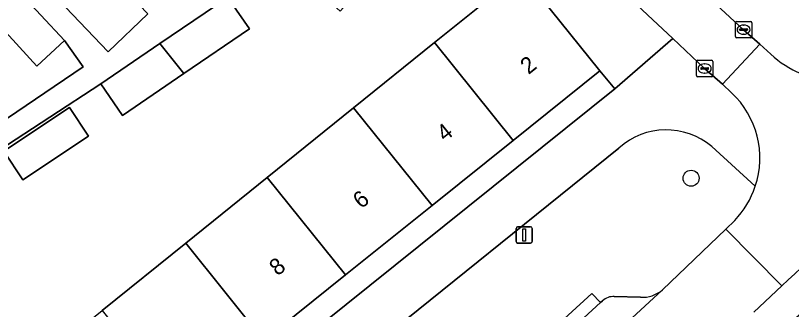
# Model space of a CAD drawing. Extents: x 162344 to 162869, y 381217 to 381818.
# Drawn here: x 162593.1 to 162640.44, y 381609.01 to 381626.94 of the extents above; entities that cross this region are included whole.
import ezdxf

# ---------------------------------------------------------------- set-up
doc = ezdxf.new("R2010")
doc.units = 0
for name, color, linetype in [('IMGEO_Boom', 7, 'Continuous'), ('IMGEO_Erf', 7, 'Continuous'), ('IMGEO_Groenvoorziening', 7, 'Continuous'), ('IMGEO_Kolk', 7, 'Continuous'), ('IMGEO_Lichtmast', 7, 'Continuous'), ('IMGEO_Pand', 7, 'Continuous'), ('IMGEO_Pand_nummerreeks', 7, 'Continuous'), ('IMGEO_Parkeervlak_open', 7, 'Continuous'), ('IMGEO_Rijbaan_lokaal_open', 7, 'Continuous'), ('IMGEO_Voetpad_open', 7, 'Continuous')]:
    doc.layers.add(name, color=color, linetype=linetype)

msp = doc.modelspace()

# ---------------------------------------------------------------- linework, layer by layer
at = {"layer": 'IMGEO_Boom'}
msp.add_circle((162634.319, 381617.015), 0.489, dxfattribs=at)
at = {"layer": 'IMGEO_Erf'}
for points in [[(162624.28, 381630.339), (162618.835, 381635.59), (162615.058, 381631.44), (162615.96, 381630.598), (162612.904, 381627.212), (162609.777, 381630.035), (162606.262, 381627.745), (162607.37, 381626.124), (162603.382, 381623.399), (162599.633, 381620.838), (162598.316, 381622.766), (162588.949, 381616.664), (162591.647, 381613.341), (162588.696, 381610.944), (162585.998, 381614.267), (162585.08, 381613.516), (162586.977, 381611.168), (162582.48, 381607.587), (162588.265, 381600.781), (162593.384, 381604.909), (162598.393, 381608.947), (162603.495, 381613.061), (162608.464, 381617.068), (162613.728, 381621.312)], [(162573.509, 381631.921), (162578.281, 381626.025), (162582.965, 381620.237), (162586.145, 381616.308), (162597.224, 381623.819), (162596.092, 381625.415), (162594.412, 381623.857), (162591.426, 381627.075)], [(162613.728, 381621.312), (162618.667, 381625.295), (162623.946, 381629.551), (162624.231, 381629.81)]]:
    msp.add_lwpolyline(points, dxfattribs=at)
for points in [[(162629.662, 381622.463), (162628.75, 381623.566), (162623.462, 381619.322), (162618.513, 381615.351), (162613.24, 381611.118), (162608.261, 381607.123), (162603.15, 381603.02), (162598.133, 381598.994), (162593.003, 381594.877), (162593.892, 381593.755)], [(162597.561, 381619.576), (162596.851, 381619.103), (162596.529, 381618.889), (162593.556, 381616.907), (162592.387, 381618.661), (162596.391, 381621.33)]]:
    msp.add_lwpolyline(points, close=True, dxfattribs=at)
at = {"layer": 'IMGEO_Groenvoorziening'}
for points in [[(162632.252, 381630.976), (162637.522, 381626.077), (162638.503, 381625.198), (162639.185, 381624.588)], [(162629.916, 381618.858), (162614.116, 381606.124), (162618.384, 381600.939), (162628.272, 381609.975), (162628.789, 381609.425), (162628.918, 381609.544)], [(162638.236, 381616.522), (162635.574, 381618.945)], [(162636.433, 381613.917), (162636.982, 381614.446)], [(162632.571, 381610.208), (162636.433, 381613.917)], [(162629.635, 381609.796), (162631.231, 381609.754)]]:
    msp.add_lwpolyline(points, dxfattribs=at)
for centre, radius, start, end in [((162643.143, 381628.73), 5.729, 226.3053, 248.3061), ((162632.795, 381615.668), 4.297, 49.6956, 132.0663), ((162633.069, 381618.226), 5.441, 315.9882, 341.7439), ((162631.345, 381611.623), 1.873, 266.5245, 310.9088), ((162629.57, 381608.834), 0.964, 86.1469, 132.5826)]:
    msp.add_arc(centre, radius, start, end, dxfattribs=at)
at = {"layer": 'IMGEO_Kolk'}
for p, q in [((162637.021, 381625.651), (162637.021, 381626.503)), ((162637.096, 381626.577), (162637.948, 381626.577)), ((162637.509, 381626.357), (162637.534, 381626.357)), ((162638.022, 381626.503), (162638.022, 381625.651)), ((162637.28, 381626.071), (162637.28, 381626.083)), ((162637.718, 381626.034), (162637.32, 381626.034)), ((162637.323, 381626.12), (162637.721, 381626.12)), ((162637.532, 381625.797), (162637.507, 381625.797)), ((162637.764, 381626.083), (162637.764, 381626.071)), ((162637.948, 381625.577), (162637.096, 381625.577)), ((162634.644, 381623.282), (162634.644, 381624.134)), ((162634.719, 381624.208), (162635.571, 381624.208)), ((162635.132, 381623.988), (162635.157, 381623.988)), ((162635.645, 381624.134), (162635.645, 381623.282)), ((162634.903, 381623.702), (162634.903, 381623.714)), ((162635.341, 381623.665), (162634.943, 381623.665)), ((162634.946, 381623.751), (162635.344, 381623.751)), ((162635.155, 381623.428), (162635.13, 381623.428)), ((162635.387, 381623.714), (162635.387, 381623.702)), ((162635.571, 381623.208), (162634.719, 381623.208))]:
    msp.add_line(p, q, dxfattribs=at)
for points in [[(162637.021, 381625.651), (162637.021, 381626.503)], [(162637.096, 381626.577), (162637.948, 381626.577)], [(162638.022, 381626.503), (162638.022, 381625.651)], [(162637.948, 381625.577), (162637.096, 381625.577)], [(162634.644, 381623.282), (162634.644, 381624.134)], [(162634.719, 381624.208), (162635.571, 381624.208)], [(162635.645, 381624.134), (162635.645, 381623.282)], [(162635.571, 381623.208), (162634.719, 381623.208)]]:
    msp.add_lwpolyline(points, dxfattribs=at)
for centre, radius, start, end in [((162637.098, 381626.501), 0.0765, 91.552, 178.448), ((162637.098, 381626.501), 0.0765, 91.552, 178.448), ((162637.946, 381626.501), 0.0765, 1.552, 88.448), ((162637.946, 381626.501), 0.0765, 1.552, 88.448), ((162637.32, 381626.08), 0.0403, 85.8775, 175.7526), ((162637.317, 381626.07), 0.0366, 178.938, 274.7102), ((162637.721, 381626.077), 0.043, 264.8664, 352.4533), ((162637.725, 381626.082), 0.0386, 1.7309, 96.639), ((162637.098, 381625.653), 0.0765, 181.552, 268.448), ((162637.098, 381625.653), 0.0765, 181.552, 268.448), ((162637.946, 381625.653), 0.0765, 271.552, 358.448), ((162637.946, 381625.653), 0.0765, 271.552, 358.448), ((162634.721, 381624.132), 0.0765, 91.552, 178.448), ((162634.721, 381624.132), 0.0765, 91.552, 178.448), ((162635.569, 381624.132), 0.0765, 1.552, 88.448), ((162635.569, 381624.132), 0.0765, 1.552, 88.448), ((162634.943, 381623.711), 0.0403, 85.8775, 175.7526), ((162634.94, 381623.701), 0.0366, 178.938, 274.7102), ((162635.344, 381623.708), 0.043, 264.8664, 352.4533), ((162635.348, 381623.713), 0.0386, 1.7309, 96.639), ((162634.721, 381623.284), 0.0765, 181.552, 268.448), ((162634.721, 381623.284), 0.0765, 181.552, 268.448), ((162635.569, 381623.284), 0.0765, 271.552, 358.448), ((162635.569, 381623.284), 0.0765, 271.552, 358.448)]:
    msp.add_arc(centre, radius, start, end, dxfattribs=at)
for centre, major_axis, ratio, start_param, end_param in [((162637.508, 381626.077), (-0.387, 0.002), 0.722429, 4.712389, 7.853982), ((162637.533, 381626.077), (-0.39, 0.002), 0.717154, 1.570796, 4.712389), ((162635.131, 381623.708), (-0.387, 0.002), 0.722429, 4.712389, 7.853982), ((162635.156, 381623.708), (-0.39, 0.002), 0.717154, 1.570796, 4.712389)]:
    msp.add_ellipse(centre, major_axis=major_axis, ratio=ratio, start_param=start_param, end_param=end_param, dxfattribs=at)
at = {"layer": 'IMGEO_Lichtmast'}
for p, q in [((162623.637, 381613.157), (162623.637, 381613.957)), ((162623.637, 381613.957), (162623.637, 381613.157)), ((162623.737, 381614.057), (162624.527, 381614.057)), ((162624.527, 381614.057), (162623.737, 381614.057)), ((162624.627, 381613.957), (162624.627, 381613.157)), ((162624.627, 381613.157), (162624.627, 381613.957)), ((162624.527, 381613.057), (162623.737, 381613.057)), ((162623.737, 381613.057), (162624.527, 381613.057))]:
    msp.add_line(p, q, dxfattribs=at)
msp.add_lwpolyline([(162624.057, 381613.932), (162624.207, 381613.932), (162624.207, 381613.182), (162624.057, 381613.182), (162624.057, 381613.932)], dxfattribs=at)
for centre, start, end in [((162623.737, 381613.957), 90, 180), ((162623.737, 381613.957), 90, 180), ((162624.527, 381613.957), 0, 90), ((162624.527, 381613.957), 360, 90), ((162623.737, 381613.157), 180, 270), ((162623.737, 381613.157), 180, 270), ((162624.527, 381613.157), 270, 0), ((162624.527, 381613.157), 270, 0)]:
    msp.add_arc(centre, 0.1, start, end, dxfattribs=at)
at = {"layer": 'IMGEO_Pand'}
for points in [[(162596.194, 381627.482), (162596.155, 381627.445), (162598.75, 381624.723), (162601.177, 381627.038), (162598.582, 381629.76)], [(162618.667, 381625.295), (162623.462, 381619.322), (162628.75, 381623.566), (162623.946, 381629.551)], [(162593.212, 381628.52), (162591.426, 381627.075), (162594.412, 381623.857), (162596.092, 381625.415)], [(162606.262, 381627.745), (162606.053, 381628.052), (162601.916, 381625.226), (162603.382, 381623.399), (162607.37, 381626.124)], [(162618.667, 381625.295), (162613.728, 381621.312), (162618.513, 381615.351), (162623.462, 381619.322)], [(162603.382, 381623.399), (162601.916, 381625.226), (162598.316, 381622.766), (162599.633, 381620.838)], [(162596.391, 381621.33), (162592.387, 381618.661), (162593.556, 381616.907), (162596.529, 381618.889), (162596.851, 381619.103), (162597.561, 381619.576)], [(162608.464, 381617.068), (162613.24, 381611.118), (162618.513, 381615.351), (162613.728, 381621.312)], [(162608.261, 381607.123), (162613.24, 381611.118), (162608.464, 381617.068), (162603.495, 381613.061)], [(162608.261, 381607.123), (162603.495, 381613.061), (162598.393, 381608.947), (162603.15, 381603.02)]]:
    msp.add_lwpolyline(points, close=True, dxfattribs=at)
at = {"layer": 'IMGEO_Parkeervlak_open'}
for points in [[(162625.936, 381604.079), (162632.571, 381610.208)], [(162639.859, 381610.448), (162638.153, 381608.851)], [(162631.231, 381609.754), (162629.635, 381609.796)], [(162628.918, 381609.544), (162628.789, 381609.425), (162625.222, 381606.148)]]:
    msp.add_lwpolyline(points, dxfattribs=at)
for centre, radius, start, end in [((162394.841, 381870.436), 357.25, 313.30209, 314.68113), ((162453.187, 381810.05), 275.288, 312.58981, 315.08241), ((162631.345, 381611.623), 1.873, 266.5245, 310.9088), ((162629.57, 381608.834), 0.964, 86.1469, 132.5826)]:
    msp.add_arc(centre, radius, start, end, dxfattribs=at)
at = {"layer": 'IMGEO_Rijbaan_lokaal_open'}
msp.add_lwpolyline([(162593.726, 381666.826), (162591.536, 381664.4), (162600.499, 381656.056), (162611.825, 381645.502), (162617.846, 381639.9), (162621.502, 381636.51), (162624.566, 381633.613), (162626.089, 381632.217), (162633.2, 381625.535), (162635.145, 381623.708), (162636.238, 381622.763), (162638.503, 381625.198), (162637.522, 381626.077), (162632.252, 381630.976), (162618.042, 381644.213)], close=True, dxfattribs=at)
for points in [[(162639.185, 381624.588), (162638.503, 381625.198), (162636.238, 381622.763), (162636.787, 381622.23)], [(162636.982, 381614.446), (162636.433, 381613.917), (162639.859, 381610.448)], [(162638.153, 381608.851), (162639.859, 381610.448), (162636.433, 381613.917), (162632.571, 381610.208), (162625.936, 381604.079)]]:
    msp.add_lwpolyline(points, dxfattribs=at)
for centre, radius, start, end in [((162643.143, 381628.73), 5.729, 226.3053, 248.3061), ((162633.039, 381618.241), 5.474, 341.7014, 46.7864), ((162633.069, 381618.226), 5.441, 315.9882, 341.7439), ((162394.841, 381870.436), 357.25, 313.30209, 314.68113)]:
    msp.add_arc(centre, radius, start, end, dxfattribs=at)
at = {"layer": 'IMGEO_Voetpad_open'}
for points in [[(162624.231, 381629.81), (162623.946, 381629.551), (162628.75, 381623.566), (162629.662, 381622.463), (162633.2, 381625.535), (162626.089, 381632.217)], [(162593.212, 381628.52), (162596.092, 381625.415), (162597.224, 381623.819), (162586.145, 381616.308), (162579.694, 381611.087), (162580.601, 381609.937), (162585.08, 381613.516), (162585.998, 381614.267), (162588.616, 381616.393), (162588.949, 381616.664), (162598.316, 381622.766), (162601.916, 381625.226), (162606.053, 381628.052)], [(162601.177, 381627.038), (162598.75, 381624.723), (162596.155, 381627.445)], [(162636.787, 381622.23), (162636.238, 381622.763), (162635.145, 381623.708), (162633.2, 381625.535), (162629.662, 381622.463), (162593.892, 381593.755), (162592.435, 381591.907), (162592.334, 381590.062)], [(162625.222, 381606.148), (162628.789, 381609.425), (162628.272, 381609.975), (162618.384, 381600.939), (162614.116, 381606.124), (162629.916, 381618.858)], [(162635.574, 381618.945), (162638.236, 381616.522)]]:
    msp.add_lwpolyline(points, dxfattribs=at)
for centre, radius, start, end in [((162633.039, 381618.241), 5.474, 341.7014, 46.7864), ((162632.795, 381615.668), 4.297, 49.6956, 132.0663), ((162453.187, 381810.05), 275.288, 312.58981, 315.08241)]:
    msp.add_arc(centre, radius, start, end, dxfattribs=at)

# ---------------------------------------------------------------- texts
at = {"layer": 'IMGEO_Pand_nummerreeks'}
for s, p in [('2', (162624.403, 381623.308)), ('4', (162619.298, 381619.212)), ('6', (162614.191, 381615.114)), ('8', (162609.087, 381611.017))]:
    msp.add_text(s, height=1, rotation=38.749, dxfattribs=at).set_placement(p)

doc.saveas('drawing.dxf')
